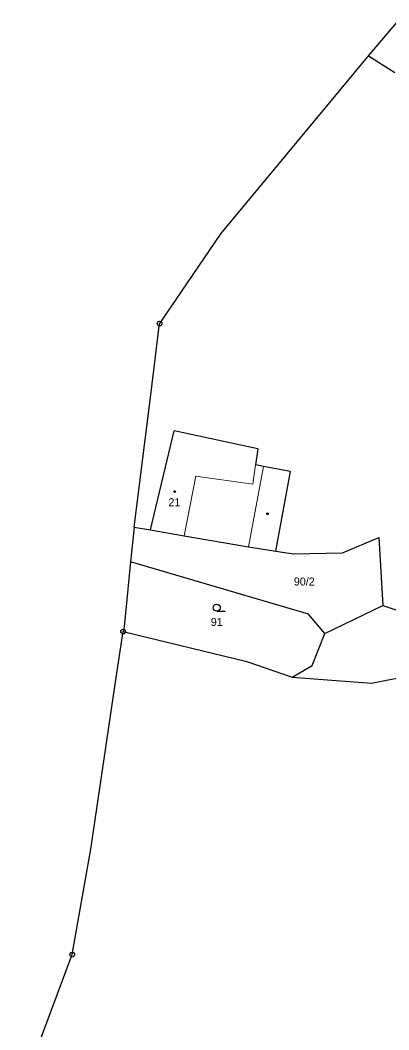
# Model space of a CAD drawing. Extents: x -601877 to -599786, y -1122905 to -1121218.
# Drawn here: x -601229.6 to -601151.3, y -1121535.2 to -1121320.8 of the extents above; entities that cross this region are included whole.
import ezdxf
from ezdxf.enums import TextEntityAlignment as Align

# ---------------------------------------------------------------- set-up
doc = ezdxf.new("R2010")
doc.units = 0
doc.header["$LTSCALE"] = 0.68
for name, color, linetype, lineweight in [('1', 7, 'Continuous', 25), ('3', 7, 'Continuous', 25), ('4', 7, 'Continuous', 13), ('5', 7, 'Continuous', 25), ('8', 7, 'Continuous', 25)]:
    doc.layers.add(name, color=color, linetype=linetype, lineweight=lineweight)
doc.layers.add('2', color=7, linetype='Continuous')

msp = doc.modelspace()

# ---------------------------------------------------------------- linework, layer by layer
at = {"layer": '1'}
for p, q in [((-601155.67, -1121328.31), (-601149.19, -1121320.77)), ((-601156.02, -1121328.71), (-601187.09, -1121366.11)), ((-601156.02, -1121328.71), (-601155.67, -1121328.31)), ((-601155.67, -1121328.31), (-601150.03, -1121331.89)), ((-601187.09, -1121366.11), (-601200.01, -1121385.19)), ((-601201.91, -1121429), (-601196.89, -1121407.98)), ((-601179.13, -1121411.78), (-601196.89, -1121407.98)), ((-601179.13, -1121411.78), (-601179.62, -1121415.22)), ((-601177.97, -1121415.52), (-601179.62, -1121415.22)), ((-601172.22, -1121416.58), (-601177.97, -1121415.52)), ((-601175.34, -1121433.51), (-601172.22, -1121416.58)), ((-601205.42, -1121428.39), (-601206.15, -1121435.82)), ((-601205.42, -1121428.39), (-601201.91, -1121429)), ((-601201.91, -1121429), (-601194.76, -1121430.24)), ((-601194.76, -1121430.24), (-601181.12, -1121432.6)), ((-601161.15, -1121433.9), (-601153.45, -1121430.6)), ((-601153.45, -1121430.6), (-601152.63, -1121445.09)), ((-601181.12, -1121432.6), (-601175.34, -1121433.51)), ((-601175.34, -1121433.51), (-601171.58, -1121434.1)), ((-601171.58, -1121434.1), (-601161.15, -1121433.9)), ((-601206.15, -1121435.82), (-601207.5, -1121449.56)), ((-601168.4, -1121446.89), (-601206.15, -1121435.82)), ((-601164.94, -1121451.02), (-601152.63, -1121445.09)), ((-601152.63, -1121445.09), (-601131.8, -1121451.85)), ((-601164.94, -1121451.02), (-601168.4, -1121446.89)), ((-601207.5, -1121449.56), (-601207.75, -1121450.58)), ((-601209.2, -1121460.37), (-601207.75, -1121450.58)), ((-601207.75, -1121450.58), (-601181.5, -1121456.98)), ((-601167.58, -1121457.78), (-601164.94, -1121451.02)), ((-601181.5, -1121456.98), (-601171.88, -1121460.3)), ((-601171.88, -1121460.3), (-601167.58, -1121457.78)), ((-601155.04, -1121461.52), (-601135.83, -1121457.82)), ((-601214.61, -1121496.79), (-601209.2, -1121460.37)), ((-601171.88, -1121460.3), (-601155.04, -1121461.52)), ((-601218.56, -1121519.2), (-601214.61, -1121496.79)), ((-601229.61, -1121548.67), (-601218.56, -1121519.2))]:
    msp.add_line(p, q, dxfattribs=at)
msp.add_lwpolyline([(-601205.42, -1121428.39), (-601201.9, -1121400.3), (-601200.01, -1121385.19)], dxfattribs=at)
at = {"layer": '3'}
msp.add_line((-601187.863, -1121446.28), (-601186.113, -1121446.28), dxfattribs=at)
msp.add_circle((-601187.8629, -1121445.5298), 0.75, dxfattribs=at)
at = {"layer": '4'}
for p, q in [((-601177.97, -1121415.52), (-601181.12, -1121432.6)), ((-601179.62, -1121415.22), (-601180.2, -1121419.29))]:
    msp.add_line(p, q, dxfattribs=at)
msp.add_lwpolyline([(-601194.76, -1121430.24), (-601192.34, -1121417.56), (-601180.2, -1121419.29)], dxfattribs=at)
at = {"layer": '5'}
for centre in [(-601196.8168, -1121420.8592), (-601177.0868, -1121425.5792)]:
    msp.add_circle(centre, 0.175, dxfattribs=at)
at = {"layer": '8'}
for centre, radius in [((-601200.01, -1121385.1899), 0.5), ((-601200.01, -1121385.1899), 0.0303), ((-601207.75, -1121450.5799), 0.5), ((-601207.75, -1121450.5799), 0.0303), ((-601218.56, -1121519.1999), 0.5), ((-601218.56, -1121519.1999), 0.0303)]:
    msp.add_circle(centre, radius, dxfattribs=at)

# ---------------------------------------------------------------- texts
at = {"layer": '2'}
for s, p in [('21', (-601196.869, -1121423.975)), ('90/2', (-601169.279, -1121440.815)), ('91', (-601187.869, -1121449.405))]:
    msp.add_text(s, height=1.7, dxfattribs=at).set_placement(p, align=Align.CENTER)

doc.saveas('drawing.dxf')
